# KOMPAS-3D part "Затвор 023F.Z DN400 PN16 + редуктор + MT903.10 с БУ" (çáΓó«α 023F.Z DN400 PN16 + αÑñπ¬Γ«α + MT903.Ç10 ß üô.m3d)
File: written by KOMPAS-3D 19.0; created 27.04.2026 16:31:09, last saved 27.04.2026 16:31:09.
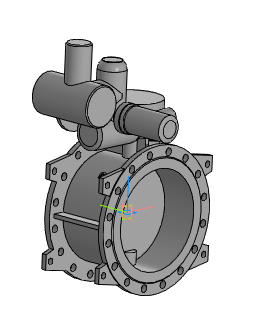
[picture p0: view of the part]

Document properties: Полное имя файла: ..\..\Затвор 023F.Z DN400-DN1600 + редуктор + МТ903\Затвор 023F.Z DN400 PN16 + редуктор + MT903.А10 с БУ.a3d

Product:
- Part/product: Затвор 023F.Z DN400 PN16 + редуктор + MT903.10 с БУ
    Масса: 325.399

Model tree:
1. Операция без истории:1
